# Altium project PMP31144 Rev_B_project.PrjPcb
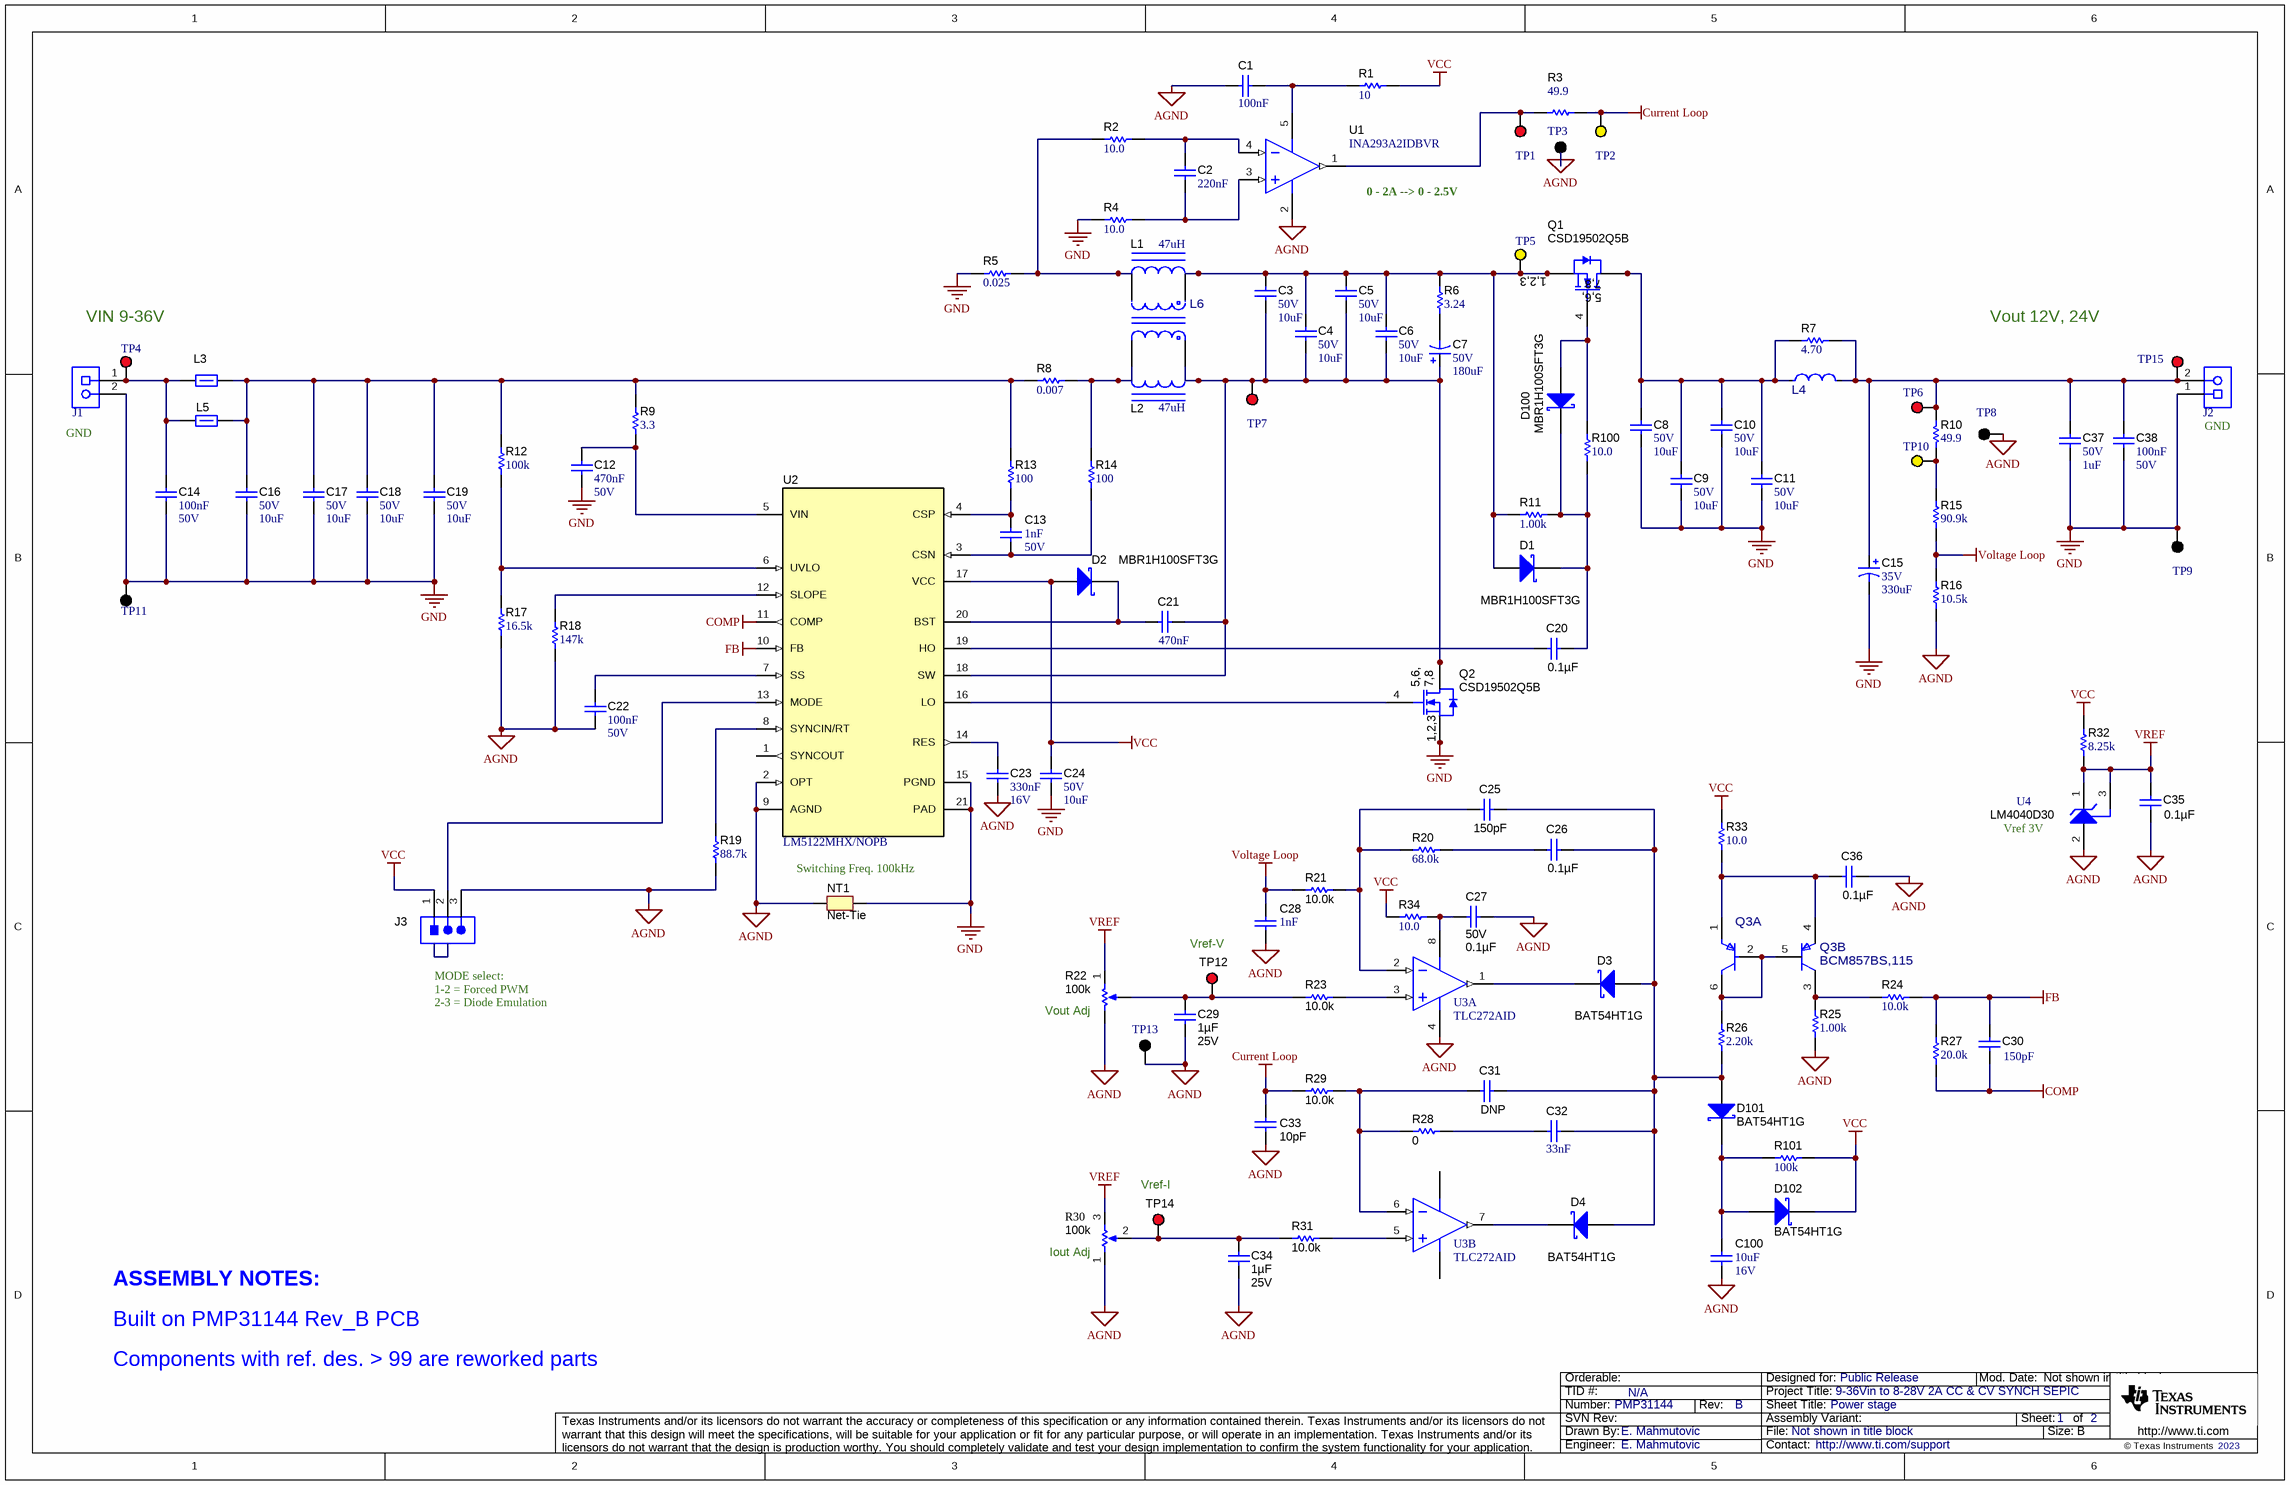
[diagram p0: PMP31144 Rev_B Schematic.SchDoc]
CopyrightYear: 2023; PCB_Layout: PMP31144; PCB_Rev: B; PRJ_Customer: Public Release; PRJ_Engineer: E. Mahmutovic; PRJ_Number: PMP31144; PRJ_Title: 9-36Vin to 8-28V 2A CC & CV SYNCH SEPIC; SCH_Rev: B; TechSupport: http://www.ti.com/support; TID: N/A
1 sheet, 114 parts. Net scope: global (net labels, ports and power ports of the same name join across sheets).
Board file: PMP31144 Rev_B_board.PcbDoc

## Sheet PMP31144 Rev_B Schematic.SchDoc: Power stage
size 431 x 279 mm; Date: Not shown in title block; ApprovedBy: Not shown in title block; CheckedBy: Not shown in title block; Author: Not shown in title block; CompanyName: Not shown in title block; DrawnBy: E. Mahmutovic; Engineer: Not shown in title block; Organization: Not shown in title block; Address1: Not shown in title block; Address2: Not shown in title block; Address3: Not shown in title block; Address4: Not shown in title block; DocumentNumber: 1; Revision: Use project parameter SCH_Rev; SheetNumber: 1; SheetTotal: 2; PageSetup: Record=PageOptions¦CenterHorizontal=True¦CenterVertical=True¦PrintScale=1.00¦XCorrection=1.00¦YCorrection=1.00¦PrintKind=0¦BorderSize=5000000¦LeftOffset=0¦BottomOffset=0¦Orientation=2¦PaperLength=1000¦PaperWidth=1000¦Scale=100¦PaperSource=15¦PrintQuality=600¦MediaType=1¦DitherType=10¦PaperKind=Letter¦PrintScaleMode=1

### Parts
C1  Cap_F: 100nF  [0603]  (hidden comment: C1608X7R1H104K080AA)
C2  Cap_F: 220nF  [0603]  (hidden comment: GRM188R71H224KAC4D)
C3  VDC_V: 50V  ValueDisplayed: 10uF  [1210_280]  (hidden comment: C3225X7R1H106M250AC)
C4  VDC_V: 50V  ValueDisplayed: 10uF  [1210_280]  (hidden comment: C3225X7R1H106M250AC)
C5  VDC_V: 50V  ValueDisplayed: 10uF  [1210_280]  (hidden comment: C3225X7R1H106M250AC)
C6  VDC_V: 50V  ValueDisplayed: 10uF  [1210_280]  (hidden comment: C3225X7R1H106M250AC)
C7  VDC_V: 50V  ValueDisplayed: 180uF  [CR_1000x1270]  (hidden comment: PCR1H181MCL1GS)
C8  VDC_V: 50V  ValueDisplayed: 10uF  [1210_280]  (hidden comment: C3225X7R1H106M250AC)
C9  VDC_V: 50V  ValueDisplayed: 10uF  [1210_280]  (hidden comment: C3225X7R1H106M250AC)
C10  VDC_V: 50V  ValueDisplayed: 10uF  [1210_280]  (hidden comment: C3225X7R1H106M250AC)
C11  VDC_V: 50V  ValueDisplayed: 10uF  [1210_280]  (hidden comment: C3225X7R1H106M250AC)
C12  Cap_F: 470nF  VDC_V: 50V  [0603]  (hidden comment: CGA3E3X7R1H474K080AE)
C13  Cap_F: 1nF  VDC_V: 50V  [0603]  (hidden comment: 885012206083)
C14  Cap_F: 100nF  VDC_V: 50V  [0603]  (hidden comment: C1608X7R1H104K080AA)
C15  VDC_V: 35V  ValueDisplayed: 330uF  [SM_RADIAL_G]  (hidden comment: EEE-FK1V331P)
C16  VDC_V: 50V  ValueDisplayed: 10uF  [1210_280]  (hidden comment: C3225X7R1H106M250AC)
C17  VDC_V: 50V  ValueDisplayed: 10uF  [1210_280]  (hidden comment: C3225X7R1H106M250AC)
C18  VDC_V: 50V  ValueDisplayed: 10uF  [1210_280]  (hidden comment: C3225X7R1H106M250AC)
C19  VDC_V: 50V  ValueDisplayed: 10uF  [1210_280]  (hidden comment: C3225X7R1H106M250AC)
C20  ValueDisplayed: 0.1µF  [0603]  (hidden comment: C0603C104K5RACAUTO)
C21  Cap_F: 470nF  [0603]  (hidden comment: CGA3E3X7R1H474K080AE)
C22  Cap_F: 100nF  VDC_V: 50V  [0603]  (hidden comment: C0603C104J5RACTU)
C23  Cap_F: 330nF  VDC_V: 16V  [0603]  (hidden comment: C0603C334K4RACTU)
C24  VDC_V: 50V  ValueDisplayed: 10uF  [1210_280]  (hidden comment: C3225X7R1H106M250AC)
C25  ValueDisplayed: 150pF  [0603]  (hidden comment: GRM1885C1H151JA01D)
C26  ValueDisplayed: 0.1µF  [0603]  (hidden comment: C0603C104K5RACAUTO)
C27  VDC_V: 50V  ValueDisplayed: 0.1µF  [0603]  (hidden comment: C0603C104K5RACAUTO)
C28  Cap_F: 1nF  [0603]  (hidden comment: 885012206083)
C29  Cap_F: 1µF  VDC_V: 25V  [0603]  (hidden comment: GRM188R71E105KA12D)
C30  ValueDisplayed: 150pF  [0603]  (hidden comment: GRM1885C1H151JA01D)
C31  DNP  [0603]
C32  Cap_F: 33nF  [0603]  (hidden comment: C0603C333J3RACTU)
C33  ValueDisplayed: 10pF  [0603]  (hidden comment: GRM1885C1H100JA01D)
C34  Cap_F: 1µF  VDC_V: 25V  [0603]  (hidden comment: GRM188R71E105KA12D)
C35  ValueDisplayed: 0.1µF  [0603]  (hidden comment: C0603C104K5RACAUTO)
C36  ValueDisplayed: 0.1µF  [0603]  (hidden comment: C0603C104K5RACAUTO)
C37  VDC_V: 50V  ValueDisplayed: 1uF  [0603]  (hidden comment: C1608X5R1H105K080AB)
C38  Cap_F: 100nF  VDC_V: 50V  [0603]  (hidden comment: C1608X7R1H104K080AA)
C100  VDC_V: 16V  ValueDisplayed: 10uF  [0805_HV]  (hidden comment: GRM21BR61C106KE15L)
D1  MBR1H100SFT3G  [SOD-123FL]
D2  MBR1H100SFT3G  [SOD-123FL]
D3  BAT54HT1G  [SOD-323]
D4  BAT54HT1G  [SOD-323]
D100  MBR1H100SFT3G  [SOD-123FL]
D101  BAT54HT1G  [SOD-323]
D102  BAT54HT1G  [SOD-323]
J1  39357-0002  [MOLEX_39357-0002]  (value not drawn)
J2  39357-0002  [MOLEX_39357-0002]  (value not drawn)
J3  PEC03SAAN  [CONN_PEC03SAAN]  (value not drawn)
L1  ValueDisplayed: 47uH  [WE-HCB_1890]  (hidden comment: 74435574700)
L2  ValueDisplayed: 47uH  [WE-HCB_1890]  (hidden comment: 74435574700)
L3  742792410  [1806_HighSpeed]  (value not drawn)
L4  XGL4020-471MEC  [FP-XGL4020-471MEC_SMT_4MM0_4MM0-MFG]  (value not drawn)
L5  742792410  [1806_HighSpeed]  (value not drawn)
L6  (no value)  [FP-LPD6235-103MRC_SMT_6MM0_6MM0-MFG]
NT1  Net-Tie  [Net-Tie_0805_HV_NoOverlay]  (net tie, no BOM)
Q1  CSD19502Q5B  [DNK0008A]
Q2  CSD19502Q5B  [DNK0008A]
Q3  BCM857BS,115  [FP-BCM857BS,115_TSSOP6-MFG]  (value not drawn)  (parts A,B of 2)
R1  ValueDisplayed: 10  [0603]  (hidden comment: CRCW060310R0JNEAHP)
R2  ValueDisplayed: 10.0  [0603]  (hidden comment: RT0603DRE0710RL)
R3  ValueDisplayed: 49.9  [0603]  (hidden comment: CRCW060349R9FKEA)
R4  ValueDisplayed: 10.0  [0603]  (hidden comment: RT0603DRE0710RL)
R5  ValueDisplayed: 0.025  [2010]  (hidden comment: CSRN2010FK25L0)
R6  ValueDisplayed: 3.24  [1206]  (hidden comment: CRCW12063R24FKEA)
R7  ValueDisplayed: 4.70  [0805_HV]  (hidden comment: RC0805FR-074R7L)
R8  ValueDisplayed: 0.007  [2512]  (hidden comment: KRL3264-C-R007-G-T1)
R9  ValueDisplayed: 3.3  [0603]  (hidden comment: CRCW06033R30JNEA)
R10  ValueDisplayed: 49.9  [0603]  (hidden comment: CRCW060349R9FKEA)
R11  ValueDisplayed: 1.00k  [0603]  (hidden comment: RT0603DRD071KL)
R12  ValueDisplayed: 100k  [0603]  (hidden comment: RC0603FR-07100KL)
R13  ValueDisplayed: 100  [0603]  (hidden comment: ERJ-3EKF1000V)
R14  ValueDisplayed: 100  [0603]  (hidden comment: ERJ-3EKF1000V)
R15  ValueDisplayed: 90.9k  [0603]  (hidden comment: CRCW060390K9FKEA)
R16  ValueDisplayed: 10.5k  [0603]  (hidden comment: CRCW060310K5FKEA)
R17  ValueDisplayed: 16.5k  [0603]  (hidden comment: RC0603FR-0716K5L)
R18  ValueDisplayed: 147k  [0603]  (hidden comment: RC0603FR-07147KL)
R19  ValueDisplayed: 88.7k  [0603]  (hidden comment: CRCW060388K7FKEA)
R20  ValueDisplayed: 68.0k  [0603]  (hidden comment: RC0603FR-0768KL)
R21  ValueDisplayed: 10.0k  [0603]  (hidden comment: CRCW060310K0FKEA)
R22  value 100k  [Bourns_PV36W]  (hidden comment: PV36W104C01B00)
R23  ValueDisplayed: 10.0k  [0603]  (hidden comment: CRCW060310K0FKEA)
R24  ValueDisplayed: 10.0k  [0603]  (hidden comment: M55342K12B10E0T)
R25  ValueDisplayed: 1.00k  [0603]  (hidden comment: RC0603FR-071KL)
R26  ValueDisplayed: 2.20k  [0603]  (hidden comment: RC0603FR-072K2L)
R27  ValueDisplayed: 20.0k  [0603]  (hidden comment: RC0603FR-0720KL)
R28  ValueDisplayed: 0  [0603]  (hidden comment: CRCW06030000Z0EA)
R29  ValueDisplayed: 10.0k  [0603]  (hidden comment: CRCW060310K0FKEA)
R30  value 100k  [Bourns_PV36W]  (hidden comment: PV36W104C01B00)
R31  ValueDisplayed: 10.0k  [0603]  (hidden comment: CRCW060310K0FKEA)
R32  ValueDisplayed: 8.25k  [0603]  (hidden comment: CRCW06038K25FKEA)
R33  ValueDisplayed: 10.0  [0603]  (hidden comment: RT0603DRE0710RL)
R34  ValueDisplayed: 10.0  [0603]  (hidden comment: RT0603DRE0710RL)
R100  ValueDisplayed: 10.0  [0603]  (hidden comment: RT0603DRE0710RL)
R101  ValueDisplayed: 100k  [0603]  (hidden comment: RC0603FR-07100KL)
TP1  5010  [Keystone5010]  (value not drawn)
TP2  5014  [Keystone5014]  (value not drawn)
TP3  5011  [Keystone5011]  (value not drawn)
TP4  5010  [Keystone5010]  (value not drawn)
TP5  5014  [Keystone5014]  (value not drawn)
TP6  5010  [Keystone5010]  (value not drawn)
TP7  5010  [Keystone5010]  (value not drawn)
TP8  5011  [Keystone5011]  (value not drawn)
TP9  5011  [Keystone5011]  (value not drawn)
TP10  5014  [Keystone5014]  (value not drawn)
TP11  5011  [Keystone5011]  (value not drawn)
TP12  5000  [Keystone5000]  (value not drawn)
TP13  5011  [Keystone5011]  (value not drawn)
TP14  5000  [Keystone5000]  (value not drawn)
TP15  5010  [Keystone5010]  (value not drawn)
U1  INA293A2IDBVR  [DBV0005A_L]
U2  LM5122MHX/NOPB  [PWP0020A_N]
U3  TLC272AID  [D0008A_L]  (parts A,B of 2)
U4  value LM4040D30  [DBZ0003A_N]  (hidden comment: LM4040D30IDBZR)

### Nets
AGND: C1.2 C22.2 C23.2 C27.1 C28.2 C29.2 C33.2 C34.2 C35.2 C36.1 C100.2 J3.3 NT1.1 R16.1 R17.1 R18.1 R19.1 R22.3(CW) R25.1 R30.1(CCW) TP3.1 TP8.1 TP13.1 U1.2(GND) U2.2(OPT) U2.9(AGND) U3.4(GND) U4.2(ANODE)
COMP: C30.2 R27.1 U2.11(COMP)
Current Loop: C33.1 R3.1 R29.1 TP2.1
FB: C30.1 R24.2 R27.2 U2.10(FB)
GND: C8.2 C9.2 C10.2 C11.2 C12.2 C14.2 C15.2(-) C16.2 C17.2 C18.2 C19.2 C24.1 C37.2 C38.2 J1.2 J2.1 NT1.2 Q2.1(S) Q2.2(S) Q2.3(S) R4.1 R5.1 TP9.1 TP11.1 U2.15(PGND) U2.21(PAD)
VCC: C24.2 D2.2(A) D102.1(K) J3.1 R1.2 R32.2 R33.2 R34.1 R101.1 U2.17(VCC)
Voltage Loop: C28.1 R15.1 R16.2 R21.1
VREF: C35.1 R22.1(CCW) R30.3(CW) R32.1 U4.1(CATHODE) U4.3(NC)
NetC1_1: C1.1 R1.1 U1.5(V+)
NetC2_1: C2.1 R2.2 U1.4(VIN-)
NetC2_2: C2.2 R4.2 U1.3(VIN+)
NetC3_1: C3.1 C4.1 C5.1 C6.1 D1.2(A) L1.2 L6.4 Q1.1(S) Q1.2(S) Q1.3(S) R6.2 R11.1 TP5.1
NetC3_2: C3.2 C4.2 C5.2 C6.2 C7.1(+) C21.1 L2.2 L6.1 Q2.5(D) Q2.6(D) Q2.7(D) Q2.8(D) Q2.9(D) TP7.1 U2.18(SW)
NetC7_2: C7.2(-) R6.1
NetC8_1: C8.1 C9.1 C10.1 C11.1 L4.1 Q1.5(D) Q1.6(D) Q1.7(D) Q1.8(D) Q1.9(D) R7.1
NetC12_1: C12.1 R9.1 U2.5(VIN)
NetC13_1: C13.1 R13.1 U2.4(CSP)
NetC13_2: C13.2 R14.1 U2.3(CSN)
NetC14_1: C14.1 J1.1 L3.1 L5.1 TP4.1
NetC15_1: C15.1(+) C37.1 C38.1 J2.2 L4.2 R7.2 R10.1 TP6.1 TP15.1
NetC16_1: C16.1 C17.1 C18.1 C19.1 L3.2 L5.2 R8.2 R9.2 R12.2 R13.2
NetC20_1: C20.1 D1.1(K) D100.1(K) R11.2 R100.1
NetC20_2: C20.2 U2.19(HO)
NetC21_2: C21.2 D2.1(K) U2.20(BST)
NetC22_1: C22.1 U2.7(SS)
NetC23_1: C23.1 U2.14(RES)
NetC25_1: C25.1 R20.1 R21.2 U3.2(IN1-)
NetC25_2: C25.2 C26.1 C31.2 C32.1 D3.2(A) D4.2(A) D101.2(A) R26.1
NetC26_2: C26.2 R20.2
NetC27_2: C27.2 R34.2 U3.8(VDD)
NetC29_1: C29.1 R22.2(WIPER) R23.1 TP12.1
NetC31_1: C31.1 R28.1 R29.2 U3.6(IN2-)
NetC32_2: C32.2 R28.2
NetC34_1: C34.1 R30.2(WIPER) R31.1 TP14.1
NetC36_2: C36.2 Q3.1(emitter_TR1) Q3.4(emitter_TR2) R33.1
NetC100_1: C100.1 D101.1(K) D102.2(A) R101.2
NetD3_1: D3.1(K) U3.1(OUT1)
NetD4_1: D4.1(K) U3.7(OUT2)
NetD100_2: D100.2(A) Q1.4(G) R100.2
NetJ3_2: J3.2 U2.13(MODE)
NetL1_1: L1.1 L6.3 R2.1 R5.2
NetL2_1: L2.1 L6.2 R8.1 R14.2
NetQ2_4: Q2.4(G) U2.16(LO)
NetQ3_2: Q3.2(base_TR1) Q3.5(base_TR2) Q3.6(collector_TR1) R26.2
NetQ3_3: Q3.3(collector_TR2) R24.1 R25.2
NetR3_2: R3.2 TP1.1 U1.1(OUT)
NetR10_2: R10.2 R15.2 TP10.1
NetR12_1: R12.1 R17.2 U2.6(UVLO)
NetR18_2: R18.2 U2.12(SLOPE)
NetR19_2: R19.2 U2.8(SYNCIN/RT)
NetR23_2: R23.2 U3.3(IN1+)
NetR31_2: R31.2 U3.5(IN2+)

Not connected (* = marked no-connect by the designer): U2 1(SYNCOUT)

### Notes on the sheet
- 0 - 2A --> 0 - 2.5V
- VIN 9-36V
- Vout 12V, 24V
- (near J1) GND
- (near J2) GND
- (near U4) Vref 3V
- (near NT1) Switching Freq. 100kHz
- Vref-V
- MODE select:
- 1-2 = Forced PWM
- 2-3 = Diode Emulation
- (near R22) Vout Adj
- Vref-I
- ASSEMBLY NOTES:
- (near R30) Iout Adj
- Built on PMP31144 Rev_B PCB
- Components with ref. des. > 99 are reworked parts

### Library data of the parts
C1 = CMP-0007044-5: CAP, CERM, 0.1 uF, 50 V, +/- 10%, X7R, 0603; Manufacturer: TDK; TaMin_C: -55°C; ESR_ohm: 29.6m; Polarized: N; SizeAreaWB_mm2: 4.68; Value1: 0.0296 ohm; U/M: EA; Value: 0.1uF; TaMax_C: 125°C; SizeZ_mm: 1; SizeX_mm: 1.6; SizeY_mm: 0.8; Value2: 50V; SizeArea_mm2: 1.28; IRMS_A: 971.99mA; AEC Category: Q200
C2 = CMP-0007445-4: CAP, CERM, 0.22 uF, 50 V, +/- 10%, X7R, 0603; Manufacturer: MuRata; TaMin_C: -55°C; Polarized: N; SizeAreaWB_mm2: 4.68; Value1: Unknown; U/M: EA; Value: 0.22uF; TaMax_C: 125°C; SizeZ_mm: 1; SizeX_mm: 1.6; SizeY_mm: 0.8; Value2: 50V; SizeArea_mm2: 1.28; AEC Category: Q200
C3-C6 C8-C11 C16-C19 C24 = CMP-0009120-1: CAP, CERM, 10 uF, 50 V, +/- 20%, X7R, 1210; Manufacturer: TDK; TaMin_C: -55°C; Polarized: N; SizeAreaWB_mm2: 14.7; Value1: Unknown; U/M: EA; Value: 10uF; TaMax_C: 125°C; SizeZ_mm: 2.8; SizeX_mm: 3.2; SizeY_mm: 2.5; Cap_Case: 1210; SizeArea_mm2: 8; Cap_F: 10µF; AEC Category: Q200
C7 = CMP-0012273-1: CAP, Aluminum Polymer, 180 uF, 50 V, +/- 20%, 0.019 ohm, SMD, 2-Leads, Dia 10.5mm, Pin Spacing 8mm SMD; Manufacturer: Nichicon; TaMin_C: -55°C; ESR_ohm: 19m; Polarized: Y; U/M: EA; Value: 180uF; TaMax_C: 125°C; Cap_Case: 10x12.7mm; CompType: Capacitor; AEC Qualified: N; Cap_F: 180µF; IRMS_A: 3.5A; AEC Category: Q200
C12 = CMP-0007097-4: CAP, CERM, 0.47 uF, 50 V, +/- 10%, X7R, AEC-Q200 Grade 1, 0603; Manufacturer: TDK; TaMin_C: -55°C; Polarized: N; SizeAreaWB_mm2: 4.68; Value1: Unknown; U/M: EA; Value: 0.47uF; TaMax_C: 125°C; SizeZ_mm: 1; SizeX_mm: 1.6; SizeY_mm: 0.8; SizeArea_mm2: 1.28; AEC Qualified: Y; AEC Category: Q200
C13 = CMP-0064933-4: CAP, CERM, 1000 pF, 50 V,+/- 10%, X7R, 0603; Manufacturer: Wurth Elektronik; TaMin_C: -55°C; Polarized: N; SizeAreaWB_mm2: 4.68; Value1: Unknown; U/M: EA; Value: 1000pF; TaMax_C: 125°C; SizeZ_mm: 1; SizeX_mm: 1.6; SizeY_mm: 0.8; SizeArea_mm2: 1.28; AEC Category: Q200
C14 C38 = CMP-0007044-5: CAP, CERM, 0.1 uF, 50 V, +/- 10%, X7R, 0603; Manufacturer: TDK; TaMin_C: -55°C; ESR_ohm: 29.6m; Polarized: N; SizeAreaWB_mm2: 4.68; Value1: 0.0296 ohm; U/M: EA; Value: 0.1uF; TaMax_C: 125°C; SizeZ_mm: 1; SizeX_mm: 1.6; SizeY_mm: 0.8; SizeArea_mm2: 1.28; IRMS_A: 971.99mA; AEC Category: Q200
C15 = CMP-0010729-1: CAP, AL, 330 uF, 35 V, +/- 20%, 0.08 ohm, AEC-Q200 Grade 2, SMD; Manufacturer: Panasonic; TaMin_C: -55°C; ESR_ohm: 80m; Polarized: Y; SizeAreaWB_mm2: 172.2; U/M: EA; Value: 330uF; TaMax_C: 105°C; SizeZ_mm: 10.2; SizeX_mm: 12; SizeY_mm: 10.3; Cap_Case: G; SizeArea_mm2: 123.6; CompType: Capacitor; Cap_F: 330µF; IRMS_A: 850mA; AEC Grade: 2; AEC Category: Q200
C20 C26 C35 C36 = CMP-0079602-1: CAP, CERM, 0.1 µF, 50 V,+/- 10%, X7R, AEC-Q200 Grade 1, 0603; Manufacturer: Kemet; TaMin_C: -55°C; Polarized: N; SizeAreaWB_mm2: 4.68; U/M: EA; Value: 0.1uF; TaMax_C: 125°C; SizeZ_mm: 1; SizeX_mm: 1.6; SizeY_mm: 0.8; Value2: 50V; SizeArea_mm2: 1.28; CompType: Capacitor; AEC Qualified: Y; Cap_F: 100nF; AEC Category: Q200
C21 = CMP-0007097-4: CAP, CERM, 0.47 uF, 50 V, +/- 10%, X7R, AEC-Q200 Grade 1, 0603; Manufacturer: TDK; TaMin_C: -55°C; Polarized: N; SizeAreaWB_mm2: 4.68; Value1: Unknown; U/M: EA; Value: 0.47uF; TaMax_C: 125°C; SizeZ_mm: 1; SizeX_mm: 1.6; SizeY_mm: 0.8; Value2: 50V; SizeArea_mm2: 1.28; AEC Qualified: Y; AEC Category: Q200
C22 = CMP-0006858-4: CAP, CERM, 0.1 uF, 50 V, +/- 5%, X7R, 0603; Manufacturer: Kemet; TaMin_C: -55°C; Polarized: N; SizeAreaWB_mm2: 4.68; Value1: Unknown; U/M: EA; Value: 0.1uF; TaMax_C: 125°C; SizeZ_mm: 1; SizeX_mm: 1.6; SizeY_mm: 0.8; SizeArea_mm2: 1.28; AEC Category: Q200
C23 = CMP-0006924-4: CAP, CERM, 0.33 uF, 16 V, +/- 10%, X7R, 0603; Manufacturer: Kemet; TaMin_C: -55°C; Polarized: N; SizeAreaWB_mm2: 4.68; Value1: Unknown; U/M: EA; Value: 0.33uF; TaMax_C: 125°C; SizeZ_mm: 1; SizeX_mm: 1.6; SizeY_mm: 0.8; SizeArea_mm2: 1.28; AEC Category: Q200
C25 C30 = CMP-0007185-4: CAP, CERM, 150 pF, 50 V, +/- 5%, C0G/NP0, 0603; Manufacturer: MuRata; TaMin_C: -55°C; Polarized: N; SizeAreaWB_mm2: 4.68; Value1: Unknown; U/M: EA; Value: 150pF; TaMax_C: 125°C; SizeZ_mm: 1; SizeX_mm: 1.6; SizeY_mm: 0.8; Value2: 50V; SizeArea_mm2: 1.28; AEC Category: Q200
C27 = CMP-0079602-1: CAP, CERM, 0.1 µF, 50 V,+/- 10%, X7R, AEC-Q200 Grade 1, 0603; Manufacturer: Kemet; TaMin_C: -55°C; Polarized: N; SizeAreaWB_mm2: 4.68; U/M: EA; Value: 0.1uF; TaMax_C: 125°C; SizeZ_mm: 1; SizeX_mm: 1.6; SizeY_mm: 0.8; SizeArea_mm2: 1.28; CompType: Capacitor; AEC Qualified: Y; Cap_F: 100nF; AEC Category: Q200
C28 = CMP-0064933-4: CAP, CERM, 1000 pF, 50 V,+/- 10%, X7R, 0603; Manufacturer: Wurth Elektronik; TaMin_C: -55°C; Polarized: N; SizeAreaWB_mm2: 4.68; Value1: Unknown; U/M: EA; Value: 1000pF; TaMax_C: 125°C; SizeZ_mm: 1; SizeX_mm: 1.6; SizeY_mm: 0.8; Value2: 50V; SizeArea_mm2: 1.28; AEC Category: Q200
C29 C34 = CMP-0007405-2: CAP, CERM, 1 uF, 25 V, +/- 10%, X7R, 0603; Manufacturer: MuRata; TaMin_C: -55°C; Polarized: N; SizeAreaWB_mm2: 4.68; Value1: Unknown; U/M: EA; Value: 1uF; TaMax_C: 125°C; SizeZ_mm: 1; SizeX_mm: 1.6; SizeY_mm: 0.8; SizeArea_mm2: 1.28; AEC Category: Q200
C31 = CMP-0007185-4: Manufacturer: MuRata; TaMin_C: -55°C; Polarized: N; TempCo: C0G/NP0; SizeAreaWB_mm2: 4.68; Value1: Unknown; U/M: EA; TaMax_C: 125°C; Tolerance_%: 5%; SizeZ_mm: 1; SizeX_mm: 1.6; SizeY_mm: 0.8; Value2: 50V; SizeArea_mm2: 1.28; AEC Category: Q200
C32 = CMP-0006923-4: CAP, CERM, 0.033 uF, 25 V, +/- 5%, X7R, 0603; Manufacturer: Kemet; TaMin_C: -55°C; Polarized: N; SizeAreaWB_mm2: 4.68; Value1: Unknown; U/M: EA; TaMax_C: 125°C; SizeZ_mm: 1; SizeX_mm: 1.6; SizeY_mm: 0.8; Value2: 25V; SizeArea_mm2: 1.28; AEC Category: Q200
C33 = CMP-0007170-2: CAP, CERM, 10 pF, 50 V, +/- 5%, C0G/NP0, 0603; Manufacturer: MuRata; TaMin_C: -55°C; Polarized: N; SizeAreaWB_mm2: 4.68; Value1: Unknown; U/M: EA; Value: 10pF; TaMax_C: 125°C; SizeZ_mm: 1; SizeX_mm: 1.6; SizeY_mm: 0.8; Value2: 50V; SizeArea_mm2: 1.28; AEC Category: Q200
C37 = CMP-0007011-5: CAP, CERM, 1 uF, 50 V, +/- 10%, X5R, 0603; Manufacturer: TDK; TaMin_C: -55°C; ESR_ohm: 5.522m; Polarized: N; SizeAreaWB_mm2: 4.68; Value1: 0.005522 ohm; U/M: EA; Value: 1uF; TaMax_C: 85°C; SizeZ_mm: 1; SizeX_mm: 1.6; SizeY_mm: 0.8; SizeArea_mm2: 1.28; Cap_F: 1µF; IRMS_A: 2.2162A; AEC Category: Q200
C100 = CMP-0008292-2: CAP, CERM, 10 uF, 16 V, +/- 10%, X5R, 0805; Manufacturer: MuRata; TaMin_C: -55°C; ESR_ohm: 8m; Polarized: N; SizeAreaWB_mm2: 6.75; Value1: 0.008 ohm; U/M: EA; Value: 10uF; TaMax_C: 85°C; SizeZ_mm: 1.45; SizeX_mm: 2; SizeY_mm: 1.25; Cap_Case: 0805; SizeArea_mm2: 2.5; Cap_F: 10µF; AEC Category: Q200
D1 D2 D100 = CMP-0028625-2: Diode, Schottky, 100 V, 1 A, SOD-123FL; Manufacturer: ON Semiconductor; Value2: 0.76V; Vr_V: 100V; RJC_CperW: 85; SizeZ_mm: 0.98; Io_A: 1A; Green_Lifecycle: Active; SizeX_mm: 3.6; AEC Category: Q101; Vf_V: 760mV; SizeAreaWB_mm2: 12.19; SizeArea_mm2: 5.94; Green_REACh: Passed; Value: 100V; TJmax_C: 175°C; SizeY_mm: 1.65
D3 D4 D101 D102 = CMP-0028455-2: Diode, Schottky, 30 V, 0.2 A, SOD-323; Manufacturer: ON Semiconductor; Vr_V: 30V; Value: 30V; SizeZ_mm: 1; Value1: 0.2A; SizeAreaWB_mm2: 8.695; Vf_V: 350mV; Io_A: 200mA; SizeX_mm: 2.7; SizeY_mm: 1.35; Green_Lifecycle: Active; AEC Category: Q101; Value2: 0.35V; SizeArea_mm2: 3.645; Green_REACh: Passed
J1 J2 = CMP-0055341-1: Terminal Block, 3.5 mm, 2x1, Tin, TH; Manufacturer: Molex; CNHeader: FALSE; Green_Lifecycle: Not Set; Green_REACh: Incomplete; CT: TRUE
J3 = CMP-0002338-1: Header, 100mil, 3x1, Tin, TH; Manufacturer: Sullins Connector Solutions; CNHeader: TRUE; Current_A: 3A; Green_Lifecycle: Not Set; Shrouded: N; Gender: Male; Green_REACh: Incomplete; Voltage_V: 1.8kV; Row_Count: 1; Pitch_mm: 2.54; CT: FALSE; Cert_UL: Y
L1 L2 = CMP-0064480-2: Inductor, Shielded Drum Core, Ferrite, 47 uH, 6.8 A, 0.0335 ohm, SMD; Manufacturer: Wurth Elektronik; Isat: 7A @ 30% inductance drop; Irms: 6.8A @ 50C rise; Green_Lifecycle: Active; SizeAreaWB_mm2: 410.06; DCR_ohm: 33.5m; Green_REACh: Passed; Value: 47uH; Imax_A: 6.8A; SizeZ_mm: 9.2; SizeX_mm: 18.3; SizeY_mm: 18.2; SizeArea_mm2: 333.06; Ind_H: 47µH; AEC Category: Q200
L3 L5 = CMP-0003159-1: Ferrite Bead, 60 ohm @ 100 MHz, 6 A, 1806; Manufacturer: Wurth Elektronik; Ztyp@1GHz_Ohm: 122.402; ZTyp@100MHz_Ohm: 60; SizeAreaWB_mm2: 14.3; DCR_ohm: 10m; Value1: 0.01 ohm; Value: 60 ohm; Imax_A: 6A; SizeZ_mm: 1.85; SizeX_mm: 4.5; SizeY_mm: 1.6; SizeArea_mm2: 7.2
L4 = CMP-0087242-1: Shielded Power Inductors; Manufacturer: Coilcraft; SizeZ_mm: 2.1mm; Symbol Name: SYM-XGL4020-471MEC; Ind_H: 470nH; Isat: 6.1A; DCR_ohm: 5.1m; Material: Composite; Irms: 19.7A; AEC Grade: Grade 1; AEC Qualified: Yes
L6 = CMP-0087230-1: COUPLED INDUCTOR
NT1 = CMP-0078142-1: Single point connection between nets.
Q1 Q2 = CMP-0000915-1: MOSFET, N-CH, 80 V, 100 A, DNK0008A (VSON-CLIP-8); Alternate Manufacturer: None; Manufacturer: Texas Instruments; SizeZ_mm: 1; ChType: N; Value2: 48 nC; VdsMax_V: 80V; SizeX_mm: 6; SizeY_mm: 5; Vgs_V: 20V; Value: 80V; SizeArea_mm2: 30; AEC Category: Q101; IdsMax_A: 100A; SizeAreaWB_mm2: 56; U/M: EA; QgTyp_nC: 48
Q3 = CMP-0090577-1: Bipolar (BJT) Transistor Array 2 PNP (Dual) Matched Pair 45V 100mA 175MHz 300mW Surface Mount 6-TSSOP; Manufacturer: Nexperia; Hfe Testic: -2mA; TJmax_C: +150°C; TaMin_C: -65°C; AEC Qualified: No; Power_W: 200mW; Number Of Elements: 2; TaMax_C: 150°C; Collector Base Voltage: -50V; Emitter Base Voltage: -5V; HfeMax: 450; Value: -45V; Rthja Max: 625K/W; Hfe Min: 200; IcRated_A: -100mA; SizeZ_mm: 1.1mm; Vcesat1_V: -200mV
R1 = CMP-0025704-3: RES, 10, 5%, 0.25 W, 0603; Manufacturer: Vishay-Dale; Power_W: 250mW; TempCo: 200 ppm/C; Value_Code: 10R0; U/M: EA; Value: 10; EIA_Code: E24; SizeX_mm: 1.6; SizeY_mm: 0.8; SizeZ_mm: 1; Value2: 0.25W; SizeArea_mm2: 1.28; VDC_V: 75V; AEC Category: Q200
R2 R4 R33 R34 R100 = CMP-0024594-3: RES, 10.0, 0.5%, 0.1 W, 0603; Manufacturer: Yageo America; Power_W: 100mW; TempCo: 50 ppm/C; Value_Code: 10R0; U/M: EA; Value: 10.0; EIA_Code: E192; Res_ohm: 10; SizeX_mm: 1.6; SizeY_mm: 0.8; SizeZ_mm: 1; Value2: 0.1W; SizeArea_mm2: 1.28; VDC_V: 75V; AEC Category: Q200
R3 R10 = CMP-0022448-2: RES, 49.9, 1%, 0.1 W, 0603; Manufacturer: Vishay-Dale; Power_W: 100mW; TempCo: 100 ppm/C; Value_Code: 49R9; U/M: EA; Value: 49.9; EIA_Code: E96; SizeX_mm: 1.6; SizeY_mm: 0.8; SizeZ_mm: 1; Value2: 0.1W; SizeArea_mm2: 1.28; VDC_V: 75V; AEC Category: Q200
R5 = CMP-0016517-2: RES, 0.025, 1%, 1 W, 2010; Manufacturer: Stackpole Electronics Inc; Power_W: 1W; TempCo: 250 ppm/C; Value_Code: R025; U/M: EA; Value: 0.025; EIA_Code: E96; Res_ohm: 25m; SizeX_mm: 5; SizeY_mm: 2.5; SizeZ_mm: 1.66; SizeArea_mm2: 12.5; AEC Category: Q200
R6 = CMP-0016971-3: RES, 3.24, 1%, 0.25 W, AEC-Q200 Grade 0, 1206; Manufacturer: Vishay-Dale; Power_W: 250mW; TempCo: 100 ppm/C; Value_Code: 3R24; Value: 3.24; EIA_Code: E96; SizeX_mm: 3.2; SizeY_mm: 1.6; SizeZ_mm: 1.35; Value2: 0.25W; SizeArea_mm2: 5.12; AEC Qualified: Y; VDC_V: 200V; AEC Category: Q200; AEC Grade: 0
R7 = CMP-0021936-2: RES, 4.70, 1%, 0.125 W, 0805; Manufacturer: Yageo America; Power_W: 125mW; TempCo: 200 ppm/C; Value_Code: 4R70; U/M: EA; Value: 4.70; Res_ohm: 4.7; SizeX_mm: 2; SizeY_mm: 1.25; SizeZ_mm: 1.45; Value2: 0.125W; SizeArea_mm2: 2.5; VDC_V: 150V; AEC Category: Q200
R8 = CMP-0016031-2: RES, 0.007, 2%, 1 W, 2512; Manufacturer: Susumu Co Ltd; Power_W: 1W; TempCo: 100 ppm/C; Value_Code: 7L000; U/M: EA; Value: 0.007; Res_ohm: 7m; SizeX_mm: 6.3; SizeY_mm: 3.2; SizeZ_mm: 0.71; SizeArea_mm2: 20.16; AEC Category: Q200
R9 = CMP-0025805-4: RES, 3.3, 5%, 0.1 W, AEC-Q200 Grade 0, 0603; Manufacturer: Vishay-Dale; Power_W: 100mW; TempCo: 200 ppm/C; Value_Code: 3R30; Value: 3.3; EIA_Code: E24; SizeX_mm: 1.6; SizeY_mm: 0.8; SizeZ_mm: 1; Value2: 0.1W; SizeArea_mm2: 1.28; AEC Qualified: Y; VDC_V: 75V; AEC Category: Q200; AEC Grade: 0
R11 = CMP-0084355-1: RES, 1.00 k, 0.5%, 0.1 W, 0603; Manufacturer: Yageo; SizeArea_mm2: 1.28; Value2: 0.1W; Res_ohm: 1k; Power_W: 100mW; EIA_Code: E192; SizeAreaWB_mm2: 4.68; TempCo: 25 ppm/C; SizeY_mm: 0.8; SizeX_mm: 1.6; AEC Qualified: N; Value_Code: 1k00; SizeZ_mm: 1; AEC Category: Q200; Value: 1.00k
R12 R101 = CMP-0022735-5: RES, 100 k, 1%, 0.1 W, 0603; Manufacturer: Yageo; Power_W: 100mW; TempCo: 100 ppm/C; Value: 100k; EIA_Code: E96; SizeX_mm: 1.6; SizeY_mm: 0.8; SizeZ_mm: 1; Value2: 0.1W; SizeArea_mm2: 1.28; AEC Qualified: N; VDC_V: 75V; AEC Category: Q200; SizeAreaWB_mm2: 4.68
R13 R14 = CMP-0022679-3: RES, 100, 1%, 0.1 W, AEC-Q200 Grade 0, 0603; Manufacturer: Panasonic; Power_W: 100mW; TempCo: 100 ppm/C; Value_Code: 100R; U/M: EA; Value: 100; EIA_Code: E96; SizeX_mm: 1.6; SizeY_mm: 0.8; SizeZ_mm: 1; Value2: 0.1W; SizeArea_mm2: 1.28; AEC Qualified: Y; AEC Grade: 0; AEC Category: Q200
R15 = CMP-0022651-4: RES, 90.9 k, 1%, 0.1 W, AEC-Q200 Grade 0, 0603; Manufacturer: Vishay-Dale; Power_W: 100mW; TempCo: 100 ppm/C; Value_Code: 90k9; Value: 90.9k; EIA_Code: E96; SizeY_mm: 0.8; SizeZ_mm: 1; Value2: 0.1W; SizeArea_mm2: 1.28; SizeX_mm: 1.6; AEC Qualified: Y; VDC_V: 75V; AEC Category: Q200; AEC Grade: 0
R16 = CMP-0022000-4: RES, 10.5 k, 1%, 0.1 W, AEC-Q200 Grade 0, 0603; Manufacturer: Vishay-Dale; Power_W: 100mW; TempCo: 100 ppm/C; Value_Code: 10k5; Value: 10.5k; EIA_Code: E96; SizeX_mm: 1.6; SizeY_mm: 0.8; SizeZ_mm: 1; Value2: 0.1W; SizeArea_mm2: 1.28; AEC Qualified: Y; VDC_V: 75V; AEC Category: Q200; AEC Grade: 0
R17 = CMP-0022829-5: RES, 16.5 k, 1%, 0.1 W, 0603; Manufacturer: Yageo; Power_W: 100mW; TempCo: 100 ppm/C; Value_Code: 16k5; Value: 16.5k; EIA_Code: E96; SizeX_mm: 1.6; SizeY_mm: 0.8; SizeZ_mm: 1; Value2: 0.1W; SizeArea_mm2: 1.28; AEC Qualified: N; VDC_V: 75V; AEC Category: Q200; SizeAreaWB_mm2: 4.68
R18 = CMP-0022800-4: RES, 147 k, 1%, 0.1 W, 0603; Manufacturer: Yageo; Power_W: 100mW; TempCo: 100 ppm/C; Value: 147k; EIA_Code: E96; SizeX_mm: 1.6; SizeY_mm: 0.8; SizeZ_mm: 1; Value2: 0.1W; SizeArea_mm2: 1.28; AEC Qualified: N; VDC_V: 75V; AEC Category: Q200; SizeAreaWB_mm2: 4.68
R19 = CMP-0022632-4: RES, 88.7 k, 1%, 0.1 W, AEC-Q200 Grade 0, 0603; Manufacturer: Vishay-Dale; Power_W: 100mW; TempCo: 100 ppm/C; Value_Code: 88k7; Value: 88.7k; EIA_Code: E96; SizeX_mm: 1.6; SizeY_mm: 0.8; SizeZ_mm: 1; Value2: 0.1W; SizeArea_mm2: 1.28; AEC Qualified: Y; VDC_V: 75V; AEC Category: Q200; AEC Grade: 0
R20 = CMP-0023239-5: RES, 68.0 k, 1%, 0.1 W, 0603; Manufacturer: Yageo; Power_W: 100mW; TempCo: 100 ppm/C; Value_Code: 68k0; Value: 68.0k; Res_ohm: 68k; SizeX_mm: 1.6; SizeY_mm: 0.8; SizeZ_mm: 1; Value2: 0.1W; SizeArea_mm2: 1.28; AEC Qualified: N; VDC_V: 75V; AEC Category: Q200; SizeAreaWB_mm2: 4.68
R21 R23 R29 R31 = CMP-0021998-4: RES, 10.0 k, 1%, 0.1 W, AEC-Q200 Grade 0, 0603; Manufacturer: Vishay-Dale; Power_W: 100mW; TempCo: 100 ppm/C; Value_Code: 10k0; Value: 10.0k; EIA_Code: E96; Res_ohm: 10k; SizeX_mm: 1.6; SizeY_mm: 0.8; SizeZ_mm: 1; Value2: 0.1W; SizeArea_mm2: 1.28; AEC Qualified: Y; VDC_V: 75V; AEC Category: Q200; AEC Grade: 0
R22 R30 = CMP-0065390-2: Potentiometer, 100k Ohm, 0.5W, TH; Manufacturer: Bourns; SizeAreaWB_mm2: 78.7499; SizeZ_mm: 12.05; SizeX_mm: 9.53; SizeY_mm: 4.83; SizeArea_mm2: 46.0299
R24 = CMP-0080488-1: RES, 10.0 k, 1%, 0.1 W, 0603; Manufacturer: TT Electronics/IRC; Power_W: 100mW; TempCo: 100 ppm/C; SizeAreaWB_mm2: 4.68; Value_Code: 10k0; Value: 10.0k; EIA_Code: E96; Res_ohm: 10k; SizeX_mm: 1.6; SizeY_mm: 0.8; SizeZ_mm: 1; Value2: 0.1W; SizeArea_mm2: 1.28; AEC Qualified: N; AEC Category: Q200
R25 = CMP-0022895-5: RES, 1.00 k, 1%, 0.1 W, 0603; Manufacturer: Yageo; Power_W: 100mW; TempCo: 100 ppm/C; Value_Code: 1k00; Value: 1.00k; EIA_Code: E96; Res_ohm: 1k; SizeX_mm: 1.6; SizeY_mm: 0.8; SizeZ_mm: 1; Value2: 0.1W; SizeArea_mm2: 1.28; AEC Qualified: N; VDC_V: 75V; AEC Category: Q200; SizeAreaWB_mm2: 4.68
R26 = CMP-0022986-5: RES, 2.20 k, 1%, 0.1 W, 0603; Manufacturer: Yageo; Power_W: 100mW; TempCo: 100 ppm/C; Value_Code: 2k20; Value: 2.20k; Res_ohm: 2.2k; SizeX_mm: 1.6; SizeY_mm: 0.8; SizeZ_mm: 1; Value2: 0.1W; SizeArea_mm2: 1.28; AEC Qualified: N; VDC_V: 75V; AEC Category: Q200; SizeAreaWB_mm2: 4.68
R27 = CMP-0022906-5: RES, 20.0 k, 1%, 0.1 W, 0603; Manufacturer: Yageo; Power_W: 100mW; TempCo: 100 ppm/C; Value_Code: 20k0; Value: 20.0k; EIA_Code: E96; Res_ohm: 20k; SizeX_mm: 1.6; SizeY_mm: 0.8; SizeZ_mm: 1; Value2: 0.1W; SizeArea_mm2: 1.28; AEC Qualified: N; VDC_V: 75V; AEC Category: Q200; SizeAreaWB_mm2: 4.68
R28 = CMP-0025697-4: RES, 0, 5%, 0.1 W, AEC-Q200 Grade 0, 0603; Manufacturer: Vishay-Dale; Power_W: 100mW; TempCo: 200 ppm/C; Value_Code: 0000; Value: 0; EIA_Code: E24; SizeX_mm: 1.6; SizeY_mm: 0.8; SizeZ_mm: 1; Value2: 0.1W; SizeArea_mm2: 1.28; AEC Qualified: Y; VDC_V: 75V; AEC Category: Q200
R32 = CMP-0022635-3: RES, 8.25 k, 1%, 0.1 W, 0603; Manufacturer: Vishay-Dale; Power_W: 100mW; TempCo: 100 ppm/C; Value_Code: 8k25; U/M: EA; Value: 8.25k; EIA_Code: E96; SizeX_mm: 1.6; SizeY_mm: 0.8; SizeZ_mm: 1; Value2: 0.1W; SizeArea_mm2: 1.28; VDC_V: 75V; AEC Category: Q200
TP1 TP4 TP6 TP7 TP15 = CMP-0055147-1: Test Point, Multipurpose, Red, TH; Manufacturer: Keystone; CNHeader: FALSE; Green_Lifecycle: Active; Green_REACh: Passed; ContactFinish: Silver; CT: TRUE
TP2 TP5 TP10 = CMP-0055151-1: Test Point, Multipurpose, Yellow, TH; Manufacturer: Keystone; CNHeader: FALSE; Green_Lifecycle: Active; Green_REACh: Passed; ContactFinish: Silver; CT: TRUE
TP3 TP8 TP9 TP11 TP13 = CMP-0055148-1: Test Point, Multipurpose, Black, TH; Manufacturer: Keystone; CNHeader: FALSE; Green_Lifecycle: Active; Green_REACh: Passed; ContactFinish: Silver; CT: TRUE
TP12 TP14 = CMP-0055137-1: Test Point, Miniature, Red, TH; Manufacturer: Keystone; ContactFinish: Silver; CNHeader: FALSE; CT: TRUE; Green_Lifecycle: Active; Green_REACh: Passed
U1 = CMP-0750214-2: INA293 High-Voltage, High Bandwidth, Unidirectional, 110-V Common-Mode, Current-Sense Amplifier, DBV0005A (SOT-23-5); Alternate PartNumber: INA293A2IDBVT; Alternate Manufacturer: Texas Instruments; SizeAreaWB_mm2: 14.82; SizeZ_mm: 1.45; CompType: IC; SizeY_mm: 2.9; SizeArea_mm2: 8.12; AEC Qualified: N; AEC Category: Q200; SizeX_mm: 2.8
U2 = CMP-0066110-3: 3-65V Wide Vin, Current Mode Synchronous Boost Controller with Multiphase Capability, PWP0020A (HTSSOP-20); Alternate PartNumber: LM5122MHE/NOPB; Manufacturer: Texas Instruments; SizeZ_mm: 1.2; SizeX_mm: 6.4; SizeY_mm: 6.5; SizeArea_mm2: 41.6; CompType: IC; SizeAreaWB_mm2: 71.4; AEC Category: Q200; AEC Qualified: N; Rating: Catalog
U3 = CMP-0043404-1: LinCMOS(TM) Precision Dual Operational Amplifier, 4 to 16 V, -40 to 85 degC, 8-pin SOIC (D8), Green (RoHS & no Sb/Br); Manufacturer: Texas Instruments; Rating: Catalog; IIB(Max)(pA): 60; Vio (25C)(Max)(mV): 5; Number of Channels: 2; CMRR(Min)(dB): 65; Offset Drift(Typ)(uV/C): 1.8; Slew Rate(Typ)(V/us): 3.6; Sub Family: General Purpose Amplifier; Iq per channel(Max)(mA): 1.6; Total Supply Voltage(Max)(+5V is 5, +/-5V is 10): 16; Total Supply Voltage(Min)(+5V is 5, +/-5V is 10): 4; GBW(Typ)(MHz): 1.7; Vn at 1kHz(Typ)(nV/rtHz): 25
U4 = CMP-0033039-1: Precision Micropower Shunt Voltage Reference, 1% accuracy, 3 V, 15 ppm / degC, 15 mA, -40 to 85 degC, 3-pin SOT-23 (DBZ), Green (RoHS & no Sb/Br); Manufacturer: Texas Instruments; Iout/Iz(Max)(mA): 15; Rating: Catalog; VO(V): 3; Initial Accuracy @ 25/deg C(%): 1; Temp Coeff(Max)(ppm/ degree C): 150; Min Iz for Regulation(uA): 65

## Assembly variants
two single inductors SEPIC: not fitted C31 L6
